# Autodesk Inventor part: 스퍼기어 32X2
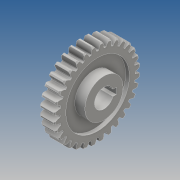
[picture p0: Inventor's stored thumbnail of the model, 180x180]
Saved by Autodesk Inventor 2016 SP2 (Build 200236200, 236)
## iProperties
Created: 2018-07
Part Number: 스퍼기어 32X2
Material: Generic
Document SubType Name: Modeling
Designer: Administrator
Density: 1 g/cm^3
Appearance: Default
Author: Administrator
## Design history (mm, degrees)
sketch "스케치1"
  geometry: L1 (-11, 0)-(11, 0); L2 (-11, 0)-(-11, 7.5); L3 (-11, 15)-(-3, 15); L4 (-3, 15)-(-3, 25); L5 (-3, 25)-(-6, 25); L6 (-6, 25)-(-6, 34); L7 (-6, 34)-(6, 34); L8 (6, 34)-(6, 25); L9 (6, 25)-(3, 25); L10 (3, 25)-(3, 15); L11 (3, 15)-(11, 15); L12 (11, 15)-(11, 7.5); L13 (-11, 7.5)-(11, 7.5); L14 (-11, 7.5)-(-11, 15); L15 (11, 7.5)-(11, 0); 3 further points
  constraints: 30 end point, 10 perpendicular, 4 point on line, 2 horizontal, 2 midpoint, 2 vertical, 1 coincident, 1 collinear, 1 vertical alignment
  dimensions: "d0" = 22 distance of L1.start L1.end; "d1" = 15 distance of L1.start L3.start; "d2" = 12 distance of L6.end L7.end; "d3" = 6 distance between parallel lines of L4 L10; "d4" = 50 diameter of L9 L1; "d5" = 68 diameter of L7 L1; "d6" = 15 diameter of L13 L1
revolve "회전1" sketch "스케치1" stored, may be unused: angle "d7" = 90 deg
sketch "스케치3"
  geometry: L1 (-2.5, 9.8)-(2.5, 9.8); L2 (2.5, 9.8)-(2.5, 7.071); L3 (-2.5, 7.071)-(-2.5, 9.8); A1 r 7.5 centre (0, 0) between (2.5, 7.071) and (-2.5, 7.071) reference
  constraints: 6 end point, 2 parallel, 2 point on circle, 1 horizontal, 1 perpendicular
  dimensions: "d23" = 5 distance of L1.start L1.end; "d24" = 2.3 distance edge to line of A1 L1
extrude "돌출2" cut sketch "스케치3" stored distance "d25" = 12; taper "d26" = 0 deg
sketch "스케치4"
  geometry: L1 (0, 0)-(3.349, 33.835); L2 (2.338, 29.407)-(2.781, 33.886); L3 (1.339, 29.47)-(1.585, 31.961); L4 (0.838, 29.488)-(1.085, 31.982); L5 (0, 0)-(0, 34); A1 r 34 centre (0, 0) between (3.349, 33.835) and (0, 34) reference; A2 r 34 centre (0, 0) between (3.349, 33.835) and (0, 34) reference; A3 r 32 centre (0, 0) between (1.085, 31.982) and (1.585, 31.961); A4 r 9.275 centre (10.004, 28.068) between (2.781, 33.886) and (0.838, 29.488); A5 r 9.275 centre (-10.004, 28.068) between (-0.838, 29.488) and (-2.781, 33.886); A6 r 29.5 centre (0, 0) between (0.838, 29.488) and (-0.838, 29.488); A7 r 34 centre (0, 0) between (2.781, 33.886) and (-2.781, 33.886)
  constraints: 16 point on circle, 10 end point, 5 centre point, 4 coincident, 3 parallel, 3 symmetric about line, 1 vertical, 1 other
  dimensions: "d30" = 64 diameter of A3; "d36" = 1.57 distance between parallel lines of L3 L1; "d37" = 1 distance between parallel lines of L3 L2; "d38" = 0.5 distance between parallel lines of L4 L3; "d39" = 5.652 deg angle of L5 L1
extrude "돌출3" cut sketch "스케치4" stored distance "d40" = 12; taper "d41" = 0 deg
chamfer "모따기4" distance "d55" = 1; stored, may be unused: second distance "d56" = 2, angle "d57" = 45 deg
fillet "모깎기4" dims "d58" = 0.5
node "솔리드1"
pattern_circular "원형 패턴4" dims angle "d60" = 360 deg
other parameters: "d27" = 1.57, "d28" = 1, "d29" = 0.5, "d33" = 1.57, "d34" = 1, "d35" = 0.5
